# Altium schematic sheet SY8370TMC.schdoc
size 127 x 101 mm
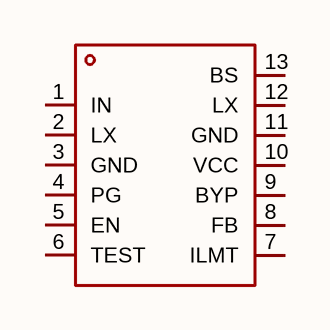
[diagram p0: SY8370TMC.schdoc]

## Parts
U?  sy8370tmc  [QFN-13_L4.0-W3.0-P0.45-BL_SY8370TMC]  (value not drawn)

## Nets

Not connected (* = marked no-connect by the designer): U? 1(IN) 2(LX) 3(GND) 4(PG) 5(EN) 6(TEST) 7(ILMT) 8(FB) 9(BYP) 10(VCC) 11(GND) 12(LX) 13(BS)

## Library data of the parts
U? = sy8370tmc: 功能类型:降压型;工作电压:4V~24V;输出电压:-;输出电流:11A;输出类型:可调;; Manufacturer: Silergy(矽力杰); AddInBom: yes; ModelId: c43388dc6bec4a39ae0533d18141e969; ModelTransform: 157.48,118.11,0,0,0,0,-5.509,0,0; Function: 降压型; Voltage - Supply: 4V~24V; Output Current: 11A; Frequency - Switching: 425kHz~575kHz; Synchronous Rectifier: 是; Number of Outputs: 1; Topology: 降压式; Quiescent Current: 140uA; Switch tube (built-in/external): 内置; Output Type: 可调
